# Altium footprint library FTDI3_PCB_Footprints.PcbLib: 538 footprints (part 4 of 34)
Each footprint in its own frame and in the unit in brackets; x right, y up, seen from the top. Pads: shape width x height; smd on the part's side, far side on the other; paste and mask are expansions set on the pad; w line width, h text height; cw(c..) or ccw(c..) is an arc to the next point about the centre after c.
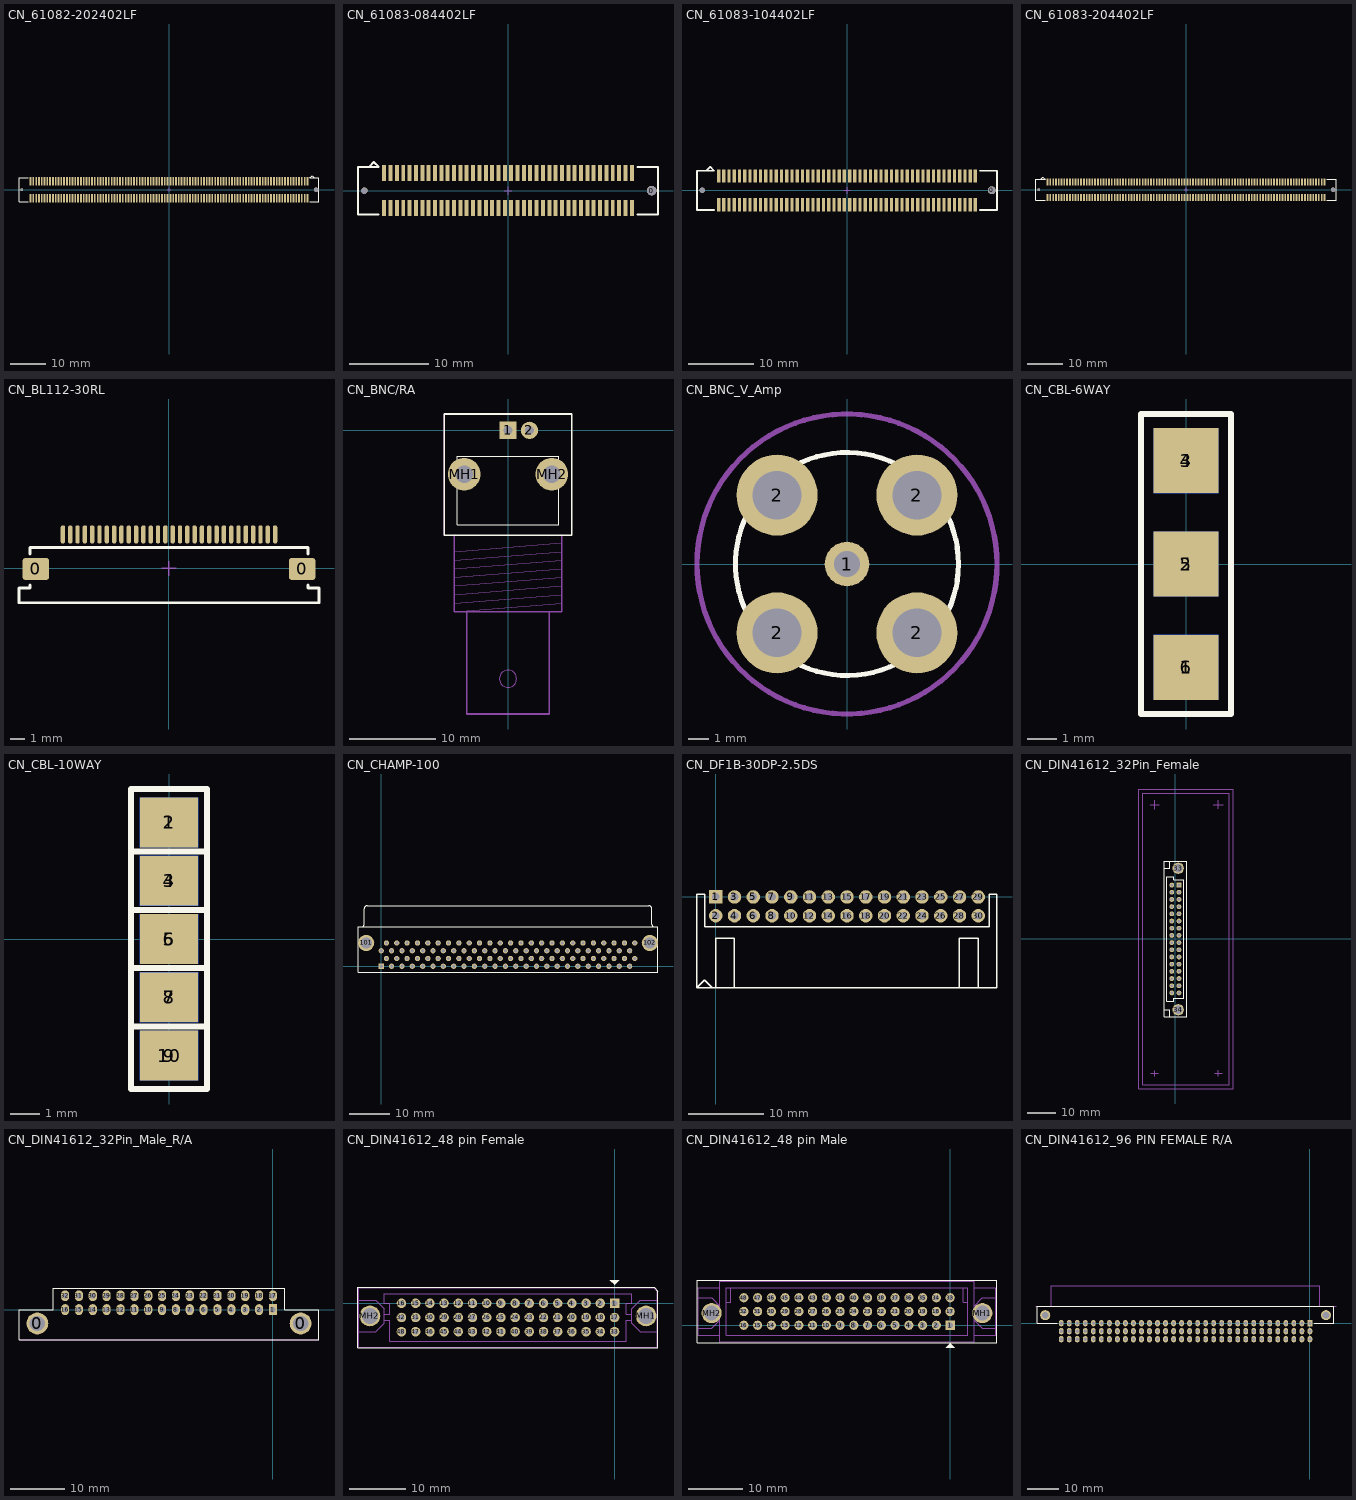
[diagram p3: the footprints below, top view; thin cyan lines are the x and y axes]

## CN_61082-202402LF [mm] "FCI, 2x100 pins, 0.8mm pitch, 7.7mm height, Board to Board Receptacle"
height 7.7
pads (202):
  round 0.8 hole 0.8 unplated: 0(-42.1,0)
  round 1.2 hole 1.2 unplated: 0(42.1,0)
  rect 0.5x2.4 smd: 1(39.6,2.4) 2(39.6,-2.4) 3(38.8,2.4) 4(38.8,-2.4) 5(38,2.4) 6(38,-2.4) 7(37.2,2.4) 8(37.2,-2.4) 9(36.4,2.4) 10(36.4,-2.4) 11(35.6,2.4) 12(35.6,-2.4) 13(34.8,2.4) 14(34.8,-2.4) 15(34,2.4) 16(34,-2.4) 17(33.2,2.4) 18(33.2,-2.4) 19(32.4,2.4) 20(32.4,-2.4) 21(31.6,2.4) 22(31.6,-2.4) 23(30.8,2.4) 24(30.8,-2.4) 25(30,2.4) 26(30,-2.4) 27(29.2,2.4) 28(29.2,-2.4) 29(28.4,2.4) 30(28.4,-2.4) 31(27.6,2.4) 32(27.6,-2.4) 33(26.8,2.4) 34(26.8,-2.4) 35(26,2.4) 36(26,-2.4) 37(25.2,2.4) 38(25.2,-2.4) 39(24.4,2.4) 40(24.4,-2.4) 41(23.6,2.4) 42(23.6,-2.4) 43(22.8,2.4) 44(22.8,-2.4) 45(22,2.4) 46(22,-2.4) 47(21.2,2.4) 48(21.2,-2.4) 49(20.4,2.4) 50(20.4,-2.4) 51(19.6,2.4) 52(19.6,-2.4) 53(18.8,2.4) 54(18.8,-2.4) 55(18,2.4) 56(18,-2.4) 57(17.2,2.4) 58(17.2,-2.4) 59(16.4,2.4) 60(16.4,-2.4) 61(15.6,2.4) 62(15.6,-2.4) 63(14.8,2.4) 64(14.8,-2.4) 65(14,2.4) 66(14,-2.4) 67(13.2,2.4) 68(13.2,-2.4) 69(12.4,2.4) 70(12.4,-2.4) 71(11.6,2.4) 72(11.6,-2.4) 73(10.8,2.4) 74(10.8,-2.4) 75(10,2.4) 76(10,-2.4) 77(9.2,2.4) 78(9.2,-2.4) 79(8.4,2.4) 80(8.4,-2.4) 81(7.6,2.4) 82(7.6,-2.4) 83(6.8,2.4) 84(6.8,-2.4) 85(6,2.4) 86(6,-2.4) 87(5.2,2.4) 88(5.2,-2.4) 89(4.4,2.4) 90(4.4,-2.4) 91(3.6,2.4) 92(3.6,-2.4) 93(2.8,2.4) 94(2.8,-2.4) 95(2,2.4) 96(2,-2.4) 97(1.2,2.4) 98(1.2,-2.4) 99(0.4,2.4) 100(0.4,-2.4) 101(-0.4,2.4) 102(-0.4,-2.4) 103(-1.2,2.4) 104(-1.2,-2.4) 105(-2,2.4) 106(-2,-2.4) 107(-2.8,2.4) 108(-2.8,-2.4) 109(-3.6,2.4) 110(-3.6,-2.4) 111(-4.4,2.4) 112(-4.4,-2.4) 113(-5.2,2.4) 114(-5.2,-2.4) 115(-6,2.4) 116(-6,-2.4) 117(-6.8,2.4) 118(-6.8,-2.4) 119(-7.6,2.4) 120(-7.6,-2.4) 121(-8.4,2.4) 122(-8.4,-2.4) 123(-9.2,2.4) 124(-9.2,-2.4) 125(-10,2.4) 126(-10,-2.4) 127(-10.8,2.4) 128(-10.8,-2.4) 129(-11.6,2.4) 130(-11.6,-2.4) 131(-12.4,2.4) 132(-12.4,-2.4) 133(-13.2,2.4) 134(-13.2,-2.4) 135(-14,2.4) 136(-14,-2.4) 137(-14.8,2.4) 138(-14.8,-2.4) 139(-15.6,2.4) 140(-15.6,-2.4) 141(-16.4,2.4) 142(-16.4,-2.4) 143(-17.2,2.4) 144(-17.2,-2.4) 145(-18,2.4) 146(-18,-2.4) 147(-18.8,2.4) 148(-18.8,-2.4) 149(-19.6,2.4) 150(-19.6,-2.4) 151(-20.4,2.4) 152(-20.4,-2.4) 153(-21.2,2.4) 154(-21.2,-2.4) 155(-22,2.4) 156(-22,-2.4) 157(-22.8,2.4) 158(-22.8,-2.4) 159(-23.6,2.4) 160(-23.6,-2.4) 161(-24.4,2.4) 162(-24.4,-2.4) 163(-25.2,2.4) 164(-25.2,-2.4) 165(-26,2.4) 166(-26,-2.4) 167(-26.8,2.4) 168(-26.8,-2.4) 169(-27.6,2.4) 170(-27.6,-2.4) 171(-28.4,2.4) 172(-28.4,-2.4) 173(-29.2,2.4) 174(-29.2,-2.4) 175(-30,2.4) 176(-30,-2.4) 177(-30.8,2.4) 178(-30.8,-2.4) 179(-31.6,2.4) 180(-31.6,-2.4) 181(-32.4,2.4) 182(-32.4,-2.4) 183(-33.2,2.4) 184(-33.2,-2.4) 185(-34,2.4) 186(-34,-2.4) 187(-34.8,2.4) 188(-34.8,-2.4) 189(-35.6,2.4) 190(-35.6,-2.4) 191(-36.4,2.4) 192(-36.4,-2.4) 193(-37.2,2.4) 194(-37.2,-2.4) 195(-38,2.4) 196(-38,-2.4) 197(-38.8,2.4) 198(-38.8,-2.4) 199(-39.6,2.4) 200(-39.6,-2.4)
Top Overlay:
  lines w0.254: -40.3,-3.425 -42.9,-3.425 -42.9,3.375 -40.3,3.375 ; 40.3,-3.4 42.9,-3.4 42.9,3.4 40.3,3.4 40.9,4 41.5,3.4
M15_Country_Yard:
  lines w0.1: -0.5,0 0.5,0 ; 0,-0.5 0,0.5

## CN_61083-084402LF [mm] "FCI, 2x40 pins, 0.8mm pitch, 7.7mm height, Board to Board Plug"
height 7.7
pads (82):
  round 0.8 hole 0.8 unplated: 0(-18.1,0)
  round 1.2 hole 1.2 unplated: 0(18.1,0)
  rect 0.5x2 smd: 1(-15.6,2.2) 2(-15.6,-2.2) 3(-14.8,2.2) 4(-14.8,-2.2) 5(-14,2.2) 6(-14,-2.2) 7(-13.2,2.2) 8(-13.2,-2.2) 9(-12.4,2.2) 10(-12.4,-2.2) 11(-11.6,2.2) 12(-11.6,-2.2) 13(-10.8,2.2) 14(-10.8,-2.2) 15(-10,2.2) 16(-10,-2.2) 17(-9.2,2.2) 18(-9.2,-2.2) 19(-8.4,2.2) 20(-8.4,-2.2) 21(-7.6,2.2) 22(-7.6,-2.2) 23(-6.8,2.2) 24(-6.8,-2.2) 25(-6,2.2) 26(-6,-2.2) 27(-5.2,2.2) 28(-5.2,-2.2) 29(-4.4,2.2) 30(-4.4,-2.2) 31(-3.6,2.2) 32(-3.6,-2.2) 33(-2.8,2.2) 34(-2.8,-2.2) 35(-2,2.2) 36(-2,-2.2) 37(-1.2,2.2) 38(-1.2,-2.2) 39(-0.4,2.2) 40(-0.4,-2.2) 41(0.4,2.2) 42(0.4,-2.2) 43(1.2,2.2) 44(1.2,-2.2) 45(2,2.2) 46(2,-2.2) 47(2.8,2.2) 48(2.8,-2.2) 49(3.6,2.2) 50(3.6,-2.2) 51(4.4,2.2) 52(4.4,-2.2) 53(5.2,2.2) 54(5.2,-2.2) 55(6,2.2) 56(6,-2.2) 57(6.8,2.2) 58(6.8,-2.2) 59(7.6,2.2) 60(7.6,-2.2) 61(8.4,2.2) 62(8.4,-2.2) 63(9.2,2.2) 64(9.2,-2.2) 65(10,2.2) 66(10,-2.2) 67(10.8,2.2) 68(10.8,-2.2) 69(11.6,2.2) 70(11.6,-2.2) 71(12.4,2.2) 72(12.4,-2.2) 73(13.2,2.2) 74(13.2,-2.2) 75(14,2.2) 76(14,-2.2) 77(14.8,2.2) 78(14.8,-2.2) 79(15.61,2.2) 80(15.6,-2.2)
Top Overlay:
  lines w0.25: -18.9,-3 -18.9,3 ; 18.9,-3 18.9,3
  lines w0.254: -18.9,-3 -16.3,-3 ; -18.9,3 -16.3,3 -16.9,3.6 ; -17.5,3 -16.9,3.6 ; 16.3,-3 18.9,-3 ; 16.3,3 18.9,3 ; -16.9,3.6 -16.9,3.6
M15_Country_Yard:
  lines w0.1: -0.5,0 0.5,0 ; 0,-0.5 0,0.5

## CN_61083-104402LF [mm] "FCI, 2x50 pins, 0.8mm pitch, 7.7mm height, Board to Board Plug"
height 7.7
pads (102):
  round 0.8 hole 0.8 unplated: 0(-22.1,0)
  round 1.2 hole 1.2 unplated: 0(22.1,0)
  rect 0.5x2 smd: 1(-19.6,2.2) 2(-19.6,-2.2) 3(-18.8,2.2) 4(-18.8,-2.2) 5(-18,2.2) 6(-18,-2.2) 7(-17.2,2.2) 8(-17.2,-2.2) 9(-16.4,2.2) 10(-16.4,-2.2) 11(-15.6,2.2) 12(-15.6,-2.2) 13(-14.8,2.2) 14(-14.8,-2.2) 15(-14,2.2) 16(-14,-2.2) 17(-13.2,2.2) 18(-13.2,-2.2) 19(-12.4,2.2) 20(-12.4,-2.2) 21(-11.6,2.2) 22(-11.6,-2.2) 23(-10.8,2.2) 24(-10.8,-2.2) 25(-10,2.2) 26(-10,-2.2) 27(-9.2,2.2) 28(-9.2,-2.2) 29(-8.4,2.2) 30(-8.4,-2.2) 31(-7.6,2.2) 32(-7.6,-2.2) 33(-6.8,2.2) 34(-6.8,-2.2) 35(-6,2.2) 36(-6,-2.2) 37(-5.2,2.2) 38(-5.2,-2.2) 39(-4.4,2.2) 40(-4.4,-2.2) 41(-3.6,2.2) 42(-3.6,-2.2) 43(-2.8,2.2) 44(-2.8,-2.2) 45(-2,2.2) 46(-2,-2.2) 47(-1.2,2.2) 48(-1.2,-2.2) 49(-0.4,2.2) 50(-0.4,-2.2) 51(0.4,2.2) 52(0.4,-2.2) 53(1.2,2.2) 54(1.2,-2.2) 55(2,2.2) 56(2,-2.2) 57(2.8,2.2) 58(2.8,-2.2) 59(3.6,2.2) 60(3.6,-2.2) 61(4.4,2.2) 62(4.4,-2.2) 63(5.2,2.2) 64(5.2,-2.2) 65(6,2.2) 66(6,-2.2) 67(6.8,2.2) 68(6.8,-2.2) 69(7.6,2.2) 70(7.6,-2.2) 71(8.4,2.2) 72(8.4,-2.2) 73(9.2,2.2) 74(9.2,-2.2) 75(10,2.2) 76(10,-2.2) 77(10.8,2.2) 78(10.8,-2.2) 79(11.6,2.2) 80(11.6,-2.2) 81(12.4,2.2) 82(12.4,-2.2) 83(13.2,2.2) 84(13.2,-2.2) 85(14,2.2) 86(14,-2.2) 87(14.8,2.2) 88(14.8,-2.2) 89(15.6,2.2) 90(15.6,-2.2) 91(16.4,2.2) 92(16.4,-2.2) 93(17.2,2.2) 94(17.2,-2.2) 95(18,2.2) 96(18,-2.2) 97(18.8,2.2) 98(18.8,-2.2) 99(19.6,2.2) 100(19.6,-2.2)
Top Overlay:
  lines w0.25: -22.9,-3 -22.9,3 ; 22.9,-3 22.9,3
  lines w0.254: -22.9,-3 -20.3,-3 ; -22.9,3 -20.3,3 -20.9,3.6 ; -21.5,3 -20.9,3.6 ; 20.3,-3 22.9,-3 ; 20.3,3 22.9,3 ; -20.9,3.6 -20.9,3.6
M15_Country_Yard:
  lines w0.1: -0.5,0 0.5,0 ; 0,-0.5 0,0.5

## CN_61083-204402LF [mm] "FCI, 2x100 pins, 0.8mm pitch, 7.7mm height, Board to Board Plug"
height 7.7
pads (202):
  round 0.8 hole 0.8 unplated: 0(-42.1,0)
  round 1.2 hole 1.2 unplated: 0(42.1,0)
  rect 0.5x2 smd: 1(-39.6,2.2) 2(-39.6,-2.2) 3(-38.8,2.2) 4(-38.8,-2.2) 5(-38,2.2) 6(-38,-2.2) 7(-37.2,2.2) 8(-37.2,-2.2) 9(-36.4,2.2) 10(-36.4,-2.2) 11(-35.6,2.2) 12(-35.6,-2.2) 13(-34.8,2.2) 14(-34.8,-2.2) 15(-34,2.2) 16(-34,-2.2) 17(-33.2,2.2) 18(-33.2,-2.2) 19(-32.4,2.2) 20(-32.4,-2.2) 21(-31.6,2.2) 22(-31.6,-2.2) 23(-30.8,2.2) 24(-30.8,-2.2) 25(-30,2.2) 26(-30,-2.2) 27(-29.2,2.2) 28(-29.2,-2.2) 29(-28.4,2.2) 30(-28.4,-2.2) 31(-27.6,2.2) 32(-27.6,-2.2) 33(-26.8,2.2) 34(-26.8,-2.2) 35(-26,2.2) 36(-26,-2.2) 37(-25.2,2.2) 38(-25.2,-2.2) 39(-24.4,2.2) 40(-24.4,-2.2) 41(-23.6,2.2) 42(-23.6,-2.2) 43(-22.8,2.2) 44(-22.8,-2.2) 45(-22,2.2) 46(-22,-2.2) 47(-21.2,2.2) 48(-21.2,-2.2) 49(-20.4,2.2) 50(-20.4,-2.2) 51(-19.6,2.2) 52(-19.6,-2.2) 53(-18.8,2.2) 54(-18.8,-2.2) 55(-18,2.2) 56(-18,-2.2) 57(-17.2,2.2) 58(-17.2,-2.2) 59(-16.4,2.2) 60(-16.4,-2.2) 61(-15.6,2.2) 62(-15.6,-2.2) 63(-14.8,2.2) 64(-14.8,-2.2) 65(-14,2.2) 66(-14,-2.2) 67(-13.2,2.2) 68(-13.2,-2.2) 69(-12.4,2.2) 70(-12.4,-2.2) 71(-11.6,2.2) 72(-11.6,-2.2) 73(-10.8,2.2) 74(-10.8,-2.2) 75(-10,2.2) 76(-10,-2.2) 77(-9.2,2.2) 78(-9.2,-2.2) 79(-8.4,2.2) 80(-8.4,-2.2) 81(-7.6,2.2) 82(-7.6,-2.2) 83(-6.8,2.2) 84(-6.8,-2.2) 85(-6,2.2) 86(-6,-2.2) 87(-5.2,2.2) 88(-5.2,-2.2) 89(-4.4,2.2) 90(-4.4,-2.2) 91(-3.6,2.2) 92(-3.6,-2.2) 93(-2.8,2.2) 94(-2.8,-2.2) 95(-2,2.2) 96(-2,-2.2) 97(-1.2,2.2) 98(-1.2,-2.2) 99(-0.4,2.2) 100(-0.4,-2.2) 101(0.4,2.2) 102(0.4,-2.2) 103(1.2,2.2) 104(1.2,-2.2) 105(2,2.2) 106(2,-2.2) 107(2.8,2.2) 108(2.8,-2.2) 109(3.6,2.2) 110(3.6,-2.2) 111(4.4,2.2) 112(4.4,-2.2) 113(5.2,2.2) 114(5.2,-2.2) 115(6,2.2) 116(6,-2.2) 117(6.8,2.2) 118(6.8,-2.2) 119(7.6,2.2) 120(7.6,-2.2) 121(8.4,2.2) 122(8.4,-2.2) 123(9.2,2.2) 124(9.2,-2.2) 125(10,2.2) 126(10,-2.2) 127(10.8,2.2) 128(10.8,-2.2) 129(11.6,2.2) 130(11.6,-2.2) 131(12.4,2.2) 132(12.4,-2.2) 133(13.2,2.2) 134(13.2,-2.2) 135(14,2.2) 136(14,-2.2) 137(14.8,2.2) 138(14.8,-2.2) 139(15.6,2.2) 140(15.6,-2.2) 141(16.4,2.2) 142(16.4,-2.2) 143(17.2,2.2) 144(17.2,-2.2) 145(18,2.2) 146(18,-2.2) 147(18.8,2.2) 148(18.8,-2.2) 149(19.6,2.2) 150(19.6,-2.2) 151(20.4,2.2) 152(20.4,-2.2) 153(21.2,2.2) 154(21.2,-2.2) 155(22,2.2) 156(22,-2.2) 157(22.8,2.2) 158(22.8,-2.2) 159(23.6,2.2) 160(23.6,-2.2) 161(24.4,2.2) 162(24.4,-2.2) 163(25.2,2.2) 164(25.2,-2.2) 165(26,2.2) 166(26,-2.2) 167(26.8,2.2) 168(26.8,-2.2) 169(27.6,2.2) 170(27.6,-2.2) 171(28.4,2.2) 172(28.4,-2.2) 173(29.2,2.2) 174(29.2,-2.2) 175(30,2.2) 176(30,-2.2) 177(30.8,2.2) 178(30.8,-2.2) 179(31.6,2.2) 180(31.6,-2.2) 181(32.4,2.2) 182(32.4,-2.2) 183(33.2,2.2) 184(33.2,-2.2) 185(34,2.2) 186(34,-2.2) 187(34.8,2.2) 188(34.8,-2.2) 189(35.6,2.2) 190(35.6,-2.2) 191(36.4,2.2) 192(36.4,-2.2) 193(37.2,2.2) 194(37.2,-2.2) 195(38,2.2) 196(38,-2.2) 197(38.8,2.2) 198(38.8,-2.2) 199(39.6,2.2) 200(39.6,-2.2)
Top Overlay:
  lines w0.25: -42.9,-3 -42.9,3 ; 42.9,-3 42.9,3
  lines w0.254: -42.9,-3 -40.3,-3 ; -42.9,3 -40.3,3 -40.9,3.6 ; -41.5,3 -40.9,3.6 ; 40.3,-3 42.9,-3 ; 40.3,3 42.9,3 ; -40.9,3.6 -40.9,3.6
M15_Country_Yard:
  lines w0.1: -0.5,0 0.5,0 ; 0,-0.5 0,0.5

## CN_BL112-30RL [mm] "FPC/FFC Connector, 30 pins, 0.5mm pitch, Suncagey"
height 2
pads (32):
  rrect25% 1.8x1.5 smd: 0(-9.1,-0.03) 0(9.1,-0.03)
  oval 0.3x1.25 smd: 1(-7.25,2.33) 2(-6.75,2.33) 3(-6.25,2.33) 4(-5.75,2.33) 5(-5.25,2.33) 6(-4.75,2.33) 7(-4.25,2.33) 8(-3.75,2.33) 9(-3.25,2.33) 10(-2.75,2.33) 11(-2.25,2.33) 12(-1.75,2.33) 13(-1.25,2.33) 14(-0.75,2.33) 15(-0.25,2.33) 16(0.25,2.33) 17(0.75,2.33) 18(1.25,2.33) 19(1.75,2.33) 20(2.25,2.33) 21(2.75,2.33) 22(3.25,2.33) 23(3.75,2.33) 24(4.25,2.33) 25(4.75,2.33) 26(5.25,2.33) 27(5.75,2.33) 28(6.25,2.33) 29(6.75,2.33) 30(7.25,2.33)
Top Overlay:
  lines w0.2: -9.5,-1.12 -9.5,-1.34 -10.25,-1.34 -10.25,-2.34 10.25,-2.34 10.25,-1.34 9.5,-1.34 9.5,-1.12 ; -9.5,1 -9.5,1.43 9.5,1.43 9.5,1
M15_Country_Yard:
  lines w0.1: -0.5,0 0.5,0 ; 0,-0.5 0,0.5

## CN_BNC/RA [mm] "BNC Connector; PCB Mount; Right Angle"
pads (4):
  rect 2x2 hole 1: 1(0,0)
  round 2 hole 1: 2(2.5,0)
  round 3.8 hole 2: MH1(-5.1,-5.1) MH2(5.1,-5.1)
Top Overlay:
  lines w0.025: -7.4,-12.2 -7.4,1.9 7.4,1.9 7.4,-12.2 6.25,-12.2 -6.25,-12.2 -7.4,-12.2 ; -5.9,-11 5.9,-11 5.9,-3 -5.9,-3 -5.9,-11
  lines w0.2: -7.4,-12.2 -6.25,-12.2 6.25,-12.2 7.4,-12.2 7.4,1.9 -7.4,1.9 -7.4,-12.2
M13_Assembly_Info:
  circle w0.025: c0,-28.9 r1
  lines w0.025: -6.25,-20.1 6.25,-19.1 ; -6.25,-19.1 6.25,-18.1 ; -6.25,-18.1 6.25,-17.1 ; -6.25,-17.1 6.25,-16.1 ; -6.25,-16.1 6.25,-15.1 ; -6.25,-15.1 6.25,-14.1 ; -6.25,-14.1 6.25,-13.1 ; 6.25,-21.1 4.8,-21.1 ; 6.25,-20.1 -6.25,-21.1 -4.8,-21.1 ; -4.8,-21.1 -4.8,-33 4.8,-33 4.8,-21.1 ; -4.8,-21.1 4.8,-21.1
  lines w0.1: -7.4,-12.2 -7.4,1.9 7.4,1.9 7.4,-12.2 -7.4,-12.2
  lines w0.2: -6.25,-12.2 -6.25,-21.1 -4.8,-21.1 ; 6.25,-12.2 6.25,-21.1 4.8,-21.1 ; -4.8,-21.1 -4.8,-33 4.8,-33 4.8,-21.1 ; -4.8,-21.1 4.8,-21.1
3D body: height 0, standoff 0, extent -7.4,-12.2 7.4,1.9

## CN_BNC_V_Amp [mm] "BNC Connector; Vertical; Amphenol; 31-5329-52RFX"
pads (5):
  round 2.2 hole 1.3: 1(0,0)
  round 4 hole 2.4: 2(-3.45,-3.4) 2(-3.45,3.4) 2(3.45,-3.4) 2(3.45,3.4)
Top Overlay:
  circle w0.25: c0,0 r5.5
M7_3D_Body:
  circle w0.254: c0,0 r7.4
M13_Assembly_Info:
  circle w0.1: c0,0 r5.5

## CN_CBL-6WAY [mm]
pads (14):
  rect 2.2x2.2 smd: 1(0,-3.5) 2(0,0) 3(0,3.5)
  rect 0x0 smd: 1(0,-3.5) 2(0,0)
  rect 0x0 smd far side: 1(0,-3.5) 2(0,0) 4(0,3.556) 4(0,3.556) 6(0,-3.556) 6(0,-3.556)
  rect 2.2x2.2 smd far side: 4(0,3.5) 5(0,0) 6(0,-3.5)
Top Overlay:
  lines w0.2: -1.524,-5.08 1.524,-5.08 1.524,5.08 -1.524,5.08 -1.524,-5.08

## CN_CBL-10WAY [mm]
pads (10):
  rect 2x1.7 smd: 1(0,4) 3(0,2) 5(0,0) 7(0,-2) 9(0,-4)
  rect 2x1.7 smd far side: 2(0,4) 4(0,2) 6(0,0) 8(0,-2) 10(0,-4)
Top Overlay:
  lines w0.2: -1.3,-3 1.3,-3 ; -1.3,-1 1.3,-1 ; -1.3,1 1.3,1 ; -1.3,3 1.3,3 ; -1.3,-5.15 1.3,-5.15 1.3,5.15 -1.3,5.15 -1.3,-5.15
Bottom Overlay:
  lines w0.2: -1.3,-3 1.3,-3 ; -1.3,-1 1.3,-1 ; -1.3,1 1.3,1 ; -1.3,3 1.3,3 ; -1.3,-5.15 1.3,-5.15 1.3,5.15 -1.3,5.15 -1.3,-5.15

## CN_CHAMP-100 [mm] "Connector; CHAMP Miniature Ribbon 050 Series I; 100 Position; Right Angle"
height 9.6
pads (102):
  rect 1.3x1.3 hole 0.8: 1(0,0)
  round 1.3 hole 0.8: 2(1.27,1.905) 3(2.54,0) 4(3.81,1.905) 5(5.08,0) 6(6.35,1.905) 7(7.62,0) 8(8.89,1.905) 9(10.16,0) 10(11.43,1.905) 11(12.7,0) 12(13.97,1.905) 13(15.24,0) 14(16.51,1.905) 15(17.78,0) 16(19.05,1.905) 17(20.32,0) 18(21.59,1.905) 19(22.86,0) 20(24.13,1.905) 21(25.4,0) 22(26.67,1.905) 23(27.94,0) 24(29.21,1.905) 25(30.48,0) 26(31.75,1.905) 27(33.02,0) 28(34.29,1.905) 29(35.56,0) 30(36.83,1.905) 31(38.1,0) 32(39.37,1.905) 33(40.64,0) 34(41.91,1.905) 35(43.18,0) 36(44.45,1.905) 37(45.72,0) 38(46.99,1.905) 39(48.26,0) 40(49.53,1.905) 41(50.8,0) 42(52.07,1.905) 43(53.34,0) 44(54.61,1.905) 45(55.88,0) 46(57.15,1.905) 47(58.42,0) 48(59.69,1.905) 49(60.96,0) 50(62.23,1.905) 51(0,3.81) 52(1.27,5.715) 53(2.54,3.81) 54(3.81,5.715) 55(5.08,3.81) 56(6.35,5.715) 57(7.62,3.81) 58(8.89,5.715) 59(10.16,3.81) 60(11.43,5.715) 61(12.7,3.81) 62(13.97,5.715) 63(15.24,3.81) 64(16.51,5.715) 65(17.78,3.81) 66(19.05,5.715) 67(20.32,3.81) 68(21.59,5.715) 69(22.86,3.81) 70(24.13,5.715) 71(25.4,3.81) 72(26.67,5.715) 73(27.94,3.81) 74(29.21,5.715) 75(30.48,3.81) 76(31.75,5.715) 77(33.02,3.81) 78(34.29,5.715) 79(35.56,3.81) 80(36.83,5.715) 81(38.1,3.81) 82(39.37,5.715) 83(40.64,3.81) 84(41.91,5.715) 85(43.18,3.81) 86(44.45,5.715) 87(45.72,3.81) 88(46.99,5.715) 89(48.26,3.81) 90(49.53,5.715) 91(50.8,3.81) 92(52.07,5.715) 93(53.34,3.81) 94(54.61,5.715) 95(55.88,3.81) 96(57.15,5.715) 97(58.42,3.81) 98(59.69,5.715) 99(60.96,3.81) 100(62.23,5.715)
  round 4 hole 2.8: 101(-3.705,5.715) 102(65.925,5.715)
Top Overlay:
  lines w0.2: -4.175,10.355 -4.175,14.155 ; -3.475,14.855 65.695,14.855 ; 66.395,10.355 66.395,14.155 ; -5.6,-1.48 -5.6,9.66 67.83,9.66 67.83,-1.48 -5.6,-1.48
  lines w0.254: -4.87,9.66 ccw(c-4.87,10.355) -4.175,10.355 ; -4.17,14.16 cw(c-3.475,14.16) -3.475,14.855 ; 65.695,14.855 cw(c65.695,14.16) 66.39,14.16 ; 66.395,10.355 ccw(c67.09,10.355) 67.09,9.66

## CN_DF1B-30DP-2.5DS [mm] "Hirose Double Row Right Angle Pin Header, 2.5mm pitch, Catalog number - 541-0642-4-**"
pads (30):
  rect 1.8x1.8 hole 1: 1(0,0)
  round 1.8 hole 1: 2(0,-2.5) 3(2.5,0) 4(2.5,-2.5) 5(5,0) 6(5,-2.5) 7(7.5,0) 8(7.5,-2.5) 9(10,0) 10(10,-2.5) 11(12.5,0) 12(12.5,-2.5) 13(15,0) 14(15,-2.5) 15(17.5,0) 16(17.5,-2.5) 17(20,0) 18(20,-2.5) 19(22.5,0) 20(22.5,-2.5) 21(25,0) 22(25,-2.5) 23(27.5,0) 24(27.5,-2.5) 25(30,0) 26(30,-2.5) 27(32.5,0) 28(32.5,-2.5) 29(35,0) 30(35,-2.5)
Top Overlay:
  lines w0.2: -0.5,-12.1 -1.5,-11.1 ; 0,-12.1 0,-5.5 2.5,-5.5 2.5,-12.1 ; 32.5,-12.1 32.5,-5.5 35,-5.5 35,-12.1 ; -2.5,-12.1 -1.5,-11.1 ; -2.5,-12.1 -2.5,-12.1 ; -2.5,-12.1 37.5,-12.1 37.5,0.4 36.5,0.4 36.5,-2.5 36.5,-4 -1.5,-4 -1.5,-2.5 -1.5,0.4 -2.5,0.4 -2.5,-12.1 ; -1.5,-11.1 -1.5,-11.1

## CN_DIN41612_32Pin_Female [mm] "Connector DIN41612; 32 pin; Female; horizontal"
height 10
pads (34):
  rect 1.7x1.7 hole 0.9: 1(1.27,19.05)
  round 1.7 hole 0.9: 2(-1.27,19.05) 3(1.27,16.51) 4(-1.27,16.51) 5(1.27,13.97) 6(-1.27,13.97) 7(1.27,11.43) 8(-1.27,11.43) 9(1.27,8.89) 10(-1.27,8.89) 11(1.27,6.35) 12(-1.27,6.35) 13(1.27,3.81) 14(-1.27,3.81) 15(1.27,1.27) 16(-1.27,1.27) 17(1.27,-1.27) 18(-1.27,-1.27) 19(1.27,-3.81) 20(-1.27,-3.81) 21(1.27,-6.35) 22(-1.27,-6.35) 23(1.27,-8.89) 24(-1.27,-8.89) 25(1.27,-11.43) 26(-1.27,-11.43) 27(1.27,-13.97) 28(-1.27,-13.97) 29(1.27,-16.51) 30(-1.27,-16.51) 31(1.27,-19.05) 32(-1.27,-19.05)
  round 4 hole 3: 33(1,25) 34(1,-25)
Top Overlay:
  lines w0.254: -4,-25 -2,-25 -2,-27.5 ; -4,25 -2,25 -2,27.5 ; -4,-27.5 -4,27.5 4,27.5 4,-27.5 -4,-27.5 ; -3,-22 -3,-20.5 -3,19 -3,22 -0.5,22 -0.5,21 3,21 3,19 3,-20.5 3,-21 -0.5,-21 -0.5,-22 -3,-22
Mechanical 2:
  lines w0.254: -13,51 -13,53 20.5,53 20.5,-53 -13,-53 -13,51.5 ; -11.5,51.5 -11.5,0 -11.5,-51.5 19.1,-51.5 19.1,51.5 -11.4,51.5 ; -8.875,47.5 -5.775,47.5 ; -8.675,-47.475 -6.1,-47.5 ; -7.35,-48.45 -7.35,-46.475 ; -7.325,45.825 -7.325,49.1 ; 13.45,47.5 16.975,47.5 ; 13.9,-47.5 16.5,-47.475 ; 15.125,46 15.125,49.1 ; 15.15,-48.575 15.15,-46.35
M13_Assembly_Info:
  text "a1" at 0.86,21.79 h1
  text "b1" at -1.74,21.73 h1
  text "b16" at -1.69,-20.27 h1
  text "a16" at 0.94,-20.23 h1

## CN_DIN41612_32Pin_Male_R/A [mm]
pads (34):
  round 4 hole 2.8: 0(-43.18,-2.54) 0(5.08,-2.54)
  rect 1.5x2 hole 1: 1(0,0)
  oval 1.5x2 hole 1: 2(-2.54,0) 3(-5.08,0) 4(-7.62,0) 5(-10.16,0) 6(-12.7,0) 7(-15.24,0) 8(-17.78,0) 9(-20.32,0) 10(-22.86,0) 11(-25.4,0) 12(-27.94,0) 13(-30.48,0) 14(-33.02,0) 15(-35.56,0) 16(-38.1,0) 17(0,2.54) 18(-2.54,2.54) 19(-5.08,2.54) 20(-7.62,2.54) 21(-10.16,2.54) 22(-12.7,2.54) 23(-15.24,2.54) 24(-17.78,2.54) 25(-20.32,2.54) 26(-22.86,2.54) 27(-25.4,2.54) 28(-27.94,2.54) 29(-30.48,2.54) 30(-33.02,2.54) 31(-35.56,2.54) 32(-38.1,2.54)
Top Overlay:
  lines w0.203: -46.55,-5.54 -46.55,0 -40.25,0 -40.25,3.93 2.15,3.93 2.15,0 8.45,0 8.45,-5.54 -46.55,-5.54
Mechanical 1:
  lines w0.1: -46.55,-5.54 8.45,-5.54
M13_Assembly_Info:
  text "a1" at 0.97,-0.39 h1.2
  text "b1" at 0.96,2.03 h1.2
  text "b16" at -41.62,1.91 h1.2
  text "a16" at -41.67,-0.56 h1.2
3D body: height 7.02, standoff -2.98, extent -45.74,-12.65 7.62,2.89

## CN_DIN41612_48 pin Female [mm] "DIN41612 series; Harting Part No. 0923 248 6825 ; Number of Positions = 48; pitch 2.54 mm"
height 11.6
pads (50):
  rect 1.7x1.7 hole 1: 1(0,0)
  round 1.7 hole 1: 2(-2.54,0) 3(-5.08,0) 4(-7.62,0) 5(-10.16,0) 6(-12.7,0) 7(-15.24,0) 8(-17.78,0) 9(-20.32,0) 10(-22.86,0) 11(-25.4,0) 12(-27.94,0) 13(-30.48,0) 14(-33.02,0) 15(-35.56,0) 16(-38.1,0) 17(0,-2.54) 18(-2.54,-2.54) 19(-5.08,-2.54) 20(-7.62,-2.54) 21(-10.16,-2.54) 22(-12.7,-2.54) 23(-15.24,-2.54) 24(-17.78,-2.54) 25(-20.32,-2.54) 26(-22.86,-2.54) 27(-25.4,-2.54) 28(-27.94,-2.54) 29(-30.48,-2.54) 30(-33.02,-2.54) 31(-35.56,-2.54) 32(-38.1,-2.54) 33(0,-5.08) 34(-2.54,-5.08) 35(-5.08,-5.08) 36(-7.62,-5.08) 37(-10.16,-5.08) 38(-12.7,-5.08) 39(-15.24,-5.08) 40(-17.78,-5.08) 41(-20.32,-5.08) 42(-22.86,-5.08) 43(-25.4,-5.08) 44(-27.94,-5.08) 45(-30.48,-5.08) 46(-33.02,-5.08) 47(-35.56,-5.08) 48(-38.1,-5.08)
  round 3.7 hole 2.8: MH1(5.635,-2.27) MH2(-43.735,-2.27)
Top Overlay:
  region: 0,3.31 -0.84,4.15 0.84,4.15
  lines w0.2: -45.87,-7.99 -45.87,2.9 7.06,2.9 7.77,2.19 7.77,-7.98 -45.87,-7.98
M13_Assembly_Info:
  lines w0.1: -45.71,-5.08 -42.72,-5.08 -41.22,-3.58 -41.22,-0.98 -42.72,0.52 -45.71,0.52 ; -41.23,-1.98 -40.19,-1.98 ; -41.22,-1.98 -41.22,-3.08 -40.18,-3.08 -40.18,-6.77 2.08,-6.77 2.08,-3.08 3.12,-3.08 3.12,-1.98 2.09,-1.98 ; -40.18,-1.98 -40.18,0.01 -41.22,0.01 -41.22,1.69 3.12,1.69 3.12,0.01 2.08,0.01 2.08,-1.98 ; 7.61,-5.08 4.62,-5.08 3.12,-3.58 3.12,-0.98 4.62,0.52 7.61,0.52 ; -45.72,-7.835 7.62,-7.835 7.62,2.13 6.995,2.755 -45.72,2.755 -45.72,-7.835
  text "a1" at 0.95,0.72 h1.2
  text "b1" at 0.89,-1.9 h1.2
  text "c1" at 0.91,-4.32 h1.2
3D body: height 11.52, standoff -3.28, extent -45.72,-7.84 7.496,2.76

## CN_DIN41612_48 pin Male [mm] "DIN41612 series; Harting Part No. 09 28 148 6903 ; Number of Positions = 48; pitch 2.54 mm"
height 15.24
pads (50):
  rect 1.7x1.7 hole 1: 1(0,0)
  round 1.7 hole 1: 2(-2.54,0) 3(-5.08,0) 4(-7.62,0) 5(-10.16,0) 6(-12.7,0) 7(-15.24,0) 8(-17.78,0) 9(-20.32,0) 10(-22.86,0) 11(-25.4,0) 12(-27.94,0) 13(-30.48,0) 14(-33.02,0) 15(-35.56,0) 16(-38.1,0) 17(0,2.54) 18(-2.54,2.54) 19(-5.08,2.54) 20(-7.62,2.54) 21(-10.16,2.54) 22(-12.7,2.54) 23(-15.24,2.54) 24(-17.78,2.54) 25(-20.32,2.54) 26(-22.86,2.54) 27(-25.4,2.54) 28(-27.94,2.54) 29(-30.48,2.54) 30(-33.02,2.54) 31(-35.56,2.54) 32(-38.1,2.54) 33(0,5.08) 34(-2.54,5.08) 35(-5.08,5.08) 36(-7.62,5.08) 37(-10.16,5.08) 38(-12.7,5.08) 39(-15.24,5.08) 40(-17.78,5.08) 41(-20.32,5.08) 42(-22.86,5.08) 43(-25.4,5.08) 44(-27.94,5.08) 45(-30.48,5.08) 46(-33.02,5.08) 47(-35.56,5.08) 48(-38.1,5.08)
  round 3.7 hole 2.8: MH1(5.95,2.24) MH2(-44.05,2.24)
Top Overlay:
  region: 0,-3.31 -0.84,-4.15 0.84,-4.15
  lines w0.2: -46.75,-3.21 8.65,-3.21 8.65,8.29 -46.75,8.29 ; -46.75,-3.2 -46.75,8.3
M13_Assembly_Info:
  lines w0.2: -46.55,-0.56 -44.07,-0.56 -42.57,0.94 ; -46.55,5.04 -44.07,5.04 -42.57,3.54 ; -42.57,-1.81 -46.55,-1.81 -46.55,6.89 -42.57,6.89 ; -41.35,4.21 -40.5,4.21 -40.5,6.89 ; 2.4,6.89 2.4,4.21 3.25,4.21 ; 4.47,-1.81 8.45,-1.81 8.45,6.89 4.47,6.89 ; 4.47,0.94 5.97,-0.56 8.45,-0.56 ; 4.47,3.54 5.97,5.04 8.45,5.04 ; -42.57,-3.01 4.47,-3.01 4.47,8.09 -42.57,8.09 -42.57,-3.01 ; -41.35,-1.81 3.25,-1.81 3.25,6.89 -41.35,6.89 -41.35,-1.81
  text "a" at 1.15,-0.45 h1.2
  text "b" at 1.17,2.05 h1.2
  text "c" at 1.16,4.64 h1.2

## CN_DIN41612_96 PIN FEMALE R/A [mm]
pads (98):
  rect 1.5x2 hole 1: 1(0,0)
  oval 1.5x2 hole 1: 2(-2.54,0) 3(-5.08,0) 4(-7.62,0) 5(-10.16,0) 6(-12.7,0) 7(-15.24,0) 8(-17.78,0) 9(-20.32,0) 10(-22.86,0) 11(-25.4,0) 12(-27.94,0) 13(-30.48,0) 14(-33.02,0) 15(-35.56,0) 16(-38.1,0) 17(-40.64,0) 18(-43.18,0) 19(-45.72,0) 20(-48.26,0) 21(-50.8,0) 22(-53.34,0) 23(-55.88,0) 24(-58.42,0) 25(-60.96,0) 26(-63.5,0) 27(-66.04,0) 28(-68.58,0) 29(-71.12,0) 30(-73.66,0) 31(-76.2,0) 32(-78.74,0) 33(0,-2.54) 34(-2.54,-2.54) 35(-5.08,-2.54) 36(-7.62,-2.54) 37(-10.16,-2.54) 38(-12.7,-2.54) 39(-15.24,-2.54) 40(-17.78,-2.54) 41(-20.32,-2.54) 42(-22.86,-2.54) 43(-25.4,-2.54) 44(-27.94,-2.54) 45(-30.48,-2.54) 46(-33.02,-2.54) 47(-35.56,-2.54) 48(-38.1,-2.54) 49(-40.64,-2.54) 50(-43.18,-2.54) 51(-45.72,-2.54) 52(-48.26,-2.54) 53(-50.8,-2.54) 54(-53.34,-2.54) 55(-55.88,-2.54) 56(-58.42,-2.54) 57(-60.96,-2.54) 58(-63.5,-2.54) 59(-66.04,-2.54) 60(-68.58,-2.54) 61(-71.12,-2.54) 62(-73.66,-2.54) 63(-76.2,-2.54) 64(-78.74,-2.54) 65(0,-5.08) 66(-2.54,-5.08) 67(-5.08,-5.08) 68(-7.62,-5.08) 69(-10.16,-5.08) 70(-12.7,-5.08) 71(-15.24,-5.08) 72(-17.78,-5.08) 73(-20.32,-5.08) 74(-22.86,-5.08) 75(-25.4,-5.08) 76(-27.94,-5.08) 77(-30.48,-5.08) 78(-33.02,-5.08) 79(-35.56,-5.08) 80(-38.1,-5.08) 81(-40.64,-5.08) 82(-43.18,-5.08) 83(-45.72,-5.08) 84(-48.26,-5.08) 85(-50.8,-5.08) 86(-53.34,-5.08) 87(-55.88,-5.08) 88(-58.42,-5.08) 89(-60.96,-5.08) 90(-63.5,-5.08) 91(-66.04,-5.08) 92(-68.58,-5.08) 93(-71.12,-5.08) 94(-73.66,-5.08) 95(-76.2,-5.08) 96(-78.74,-5.08)
  round 3.2 hole 2.1: MH1(5.08,2.54) MH2(-83.82,2.54)
Top Overlay:
  lines w0.2: -80.075,0 -86.295,0 -86.295,5.4 7.585,5.4 7.585,0 1.315,0
Mechanical 1:
  lines w0.2: -86.74,5.41 8.26,5.41
M13_Assembly_Info:
  lines w0.1: -81.865,5.4 -81.865,11.9 ; -81.855,11.9 3.135,11.9 3.135,5.4
  text "c32" at -80.66,-4.02 h1
  text "b32" at -80.66,-1.43 h1
  text "a32" at -80.68,1.56 h1
  text "a1" at 0.92,0.62 h1
  text "b1" at 0.93,-2.09 h1
  text "c1" at 0.93,-4.44 h1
